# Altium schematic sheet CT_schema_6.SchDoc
size 297 x 173 mm
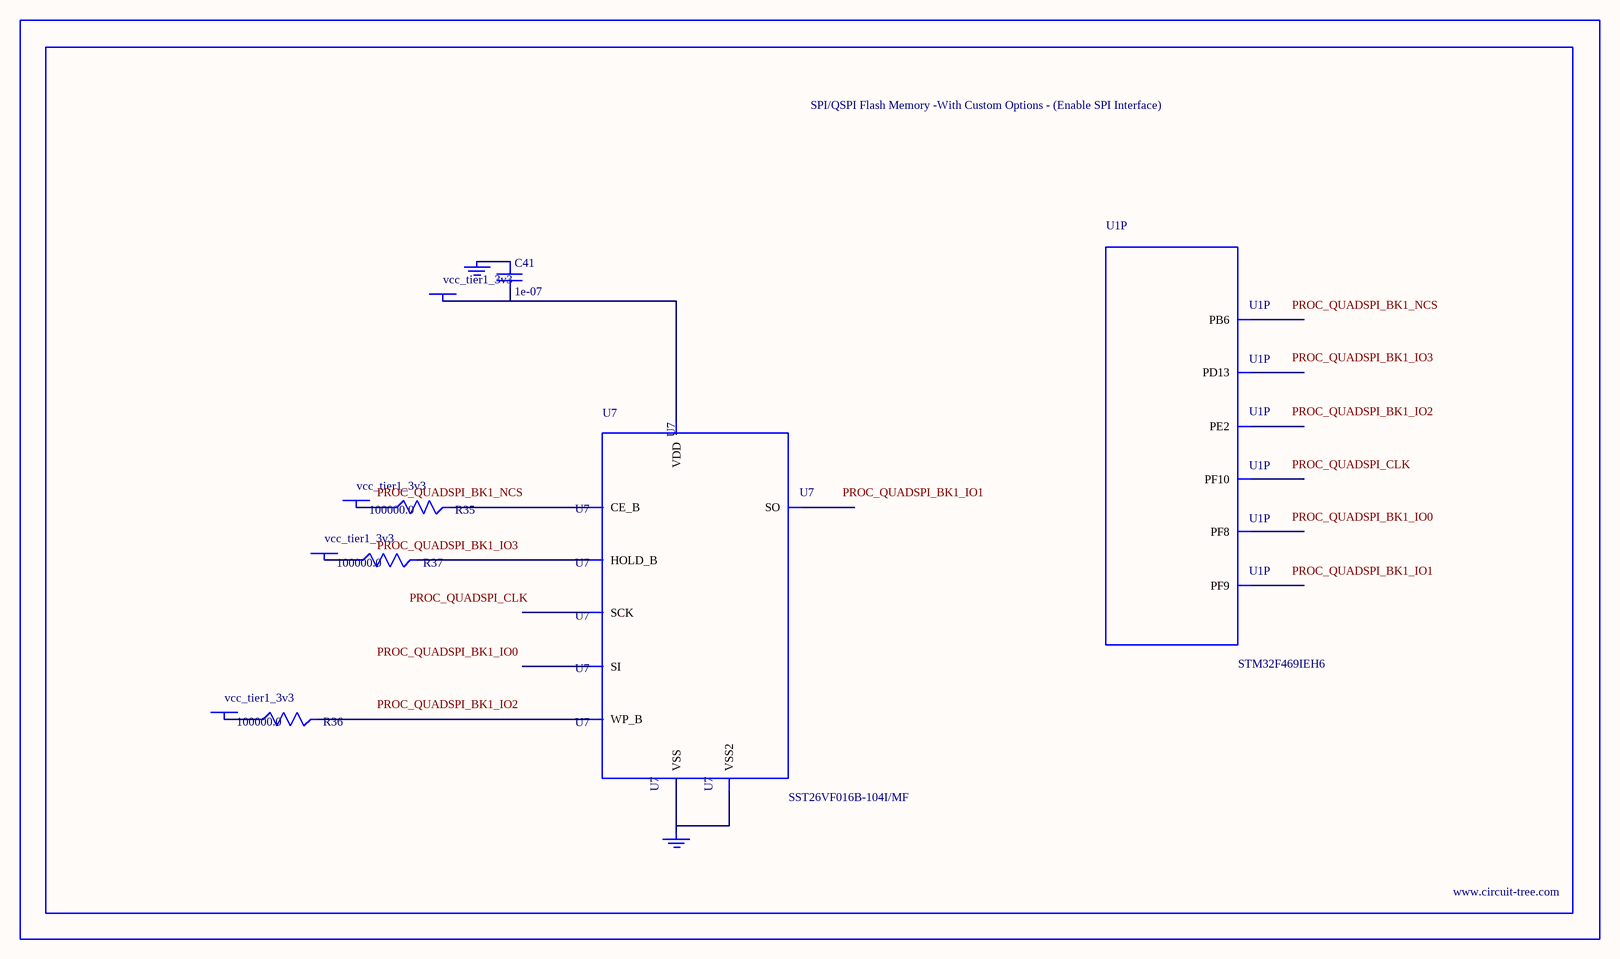
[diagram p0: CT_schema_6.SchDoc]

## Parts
BORDER5  (no value)
C41  1e-07  [C0402]
GND_INSTANCE_5_0  (no value)
GND_INSTANCE_5_1  (no value)
POWER_INSTANCE_5_0  vcc_tier1_3v3
POWER_INSTANCE_5_1  vcc_tier1_3v3
POWER_INSTANCE_5_2  vcc_tier1_3v3
POWER_INSTANCE_5_3  vcc_tier1_3v3
R35  100000.0  [R0603]
R36  100000.0  [R0603]
R37  100000.0  [R0603]
U1  STM32F469IEH6  [UFBGA176]  (part P of 16)
U7  SST26VF016B-104I/MF  [WFDN-8]

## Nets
NetC41_1: C41.1 GND_INSTANCE_5_0.0(GND)
NetC41_2: C41.2 POWER_INSTANCE_5_3.0(PWR) U7.8(VDD)
NetGND_INSTANCE_5_1_0: GND_INSTANCE_5_1.0(GND) U7.4(VSS) U7.9(VSS2)
NetPOWER_INSTANCE_5_0_0: POWER_INSTANCE_5_0.0(PWR) R35.1
NetPOWER_INSTANCE_5_1_0: POWER_INSTANCE_5_1.0(PWR) R36.1
NetPOWER_INSTANCE_5_2_0: POWER_INSTANCE_5_2.0(PWR) R37.1
NetR35_2: R35.2 U7.1(CE_B)
NetR36_2: R36.2 U7.3(WP_B)
NetR37_2: R37.2 U7.7(HOLD_B)

Not connected (* = marked no-connect by the designer): U1 A2(PE2) B6(PB6) L1(PF10) L2(PF9) L3(PF8) M15(PD13); U7 2(SO) 5(SI) 6(SCK)

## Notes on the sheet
- Labels drawn without touching a wire or pin: PROC_QUADSPI_BK1_IO0, PROC_QUADSPI_BK1_IO1, PROC_QUADSPI_BK1_IO2, PROC_QUADSPI_BK1_IO3, PROC_QUADSPI_BK1_NCS, PROC_QUADSPI_CLK

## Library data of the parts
BORDER5 = BORDER_PAGE5
C41 = C0402C104K3RACTU
GND_INSTANCE_5_0 GND_INSTANCE_5_1 = GND
POWER_INSTANCE_5_0-POWER_INSTANCE_5_3 = PWR
R35-R37 = RC0603JR-07100KL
